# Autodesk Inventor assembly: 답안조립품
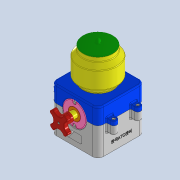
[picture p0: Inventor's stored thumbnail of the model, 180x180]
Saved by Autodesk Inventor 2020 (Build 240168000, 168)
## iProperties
Created: 2022-03
Part Number: 답안조립품
Document SubType Name: Assembly
Designer: Administrator
Author: Administrator
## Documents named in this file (11)
- C:\Users\Administrator\Desktop\720306V1011\답안조립품.iam
- C:\Users\Administrator\Desktop\720306V1011\본체.ipt
- C:\Users\Administrator\Desktop\720306V1011\본체커버.ipt
- C:\Users\Administrator\Desktop\720306V1011\앞커버.ipt
- C:\Users\Administrator\Desktop\720306V1011\핸들축.ipt
- C:\Users\Administrator\Desktop\720306V1011\베어링 부시.ipt
- C:\Users\Administrator\Desktop\720306V1011\용기.ipt
- C:\Users\Administrator\Desktop\720306V1011\용기캡.ipt
- C:\Users\Administrator\Desktop\720306V1011\핸들.ipt
- C:\Users\Administrator\Desktop\720306V1011\볼트 M3x12.ipt
- C:\Users\Administrator\Desktop\720306V1011\볼트 M4x12.ipt
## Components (2 placed, 2 different names)
1. 핸들축:1 — 각도:1
2. 핸들:1 — 각도:1
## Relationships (1: Angle 1)
- 각도:1 [Angle]: 핸들축:1 ↔ 핸들:1
